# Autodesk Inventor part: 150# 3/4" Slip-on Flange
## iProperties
Company: WSRC - Nonproliferation Technologies Section
Title: 150# 3/4" Slip-on Flange
Subject: Standard Parts
Author: Mike Maxwell
Revision Number: 0
Shininess: 60.0
PropertySet Name: _Private Model Information
Created: 2001-04
Part Number: 150# 3/4" Slip-on Flange
Project: Standard Parts
Material: Stainless Steel, 304L
Description: 150# Slip-on Flange
Document SubType Name: Modeling
Designer: Mike Maxwell
Engineer: Mike Maxwell
Control State: 0
Master: False
Checked Out: False
PropertySet Name: Design Tracking Control
Density: 8.03
Volumn: 98.91173487445732
Area: 242.82835336465928
PropertySet Name: Model Information
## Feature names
1. Revolution1
2. Hole1
3. Circular Pattern1
